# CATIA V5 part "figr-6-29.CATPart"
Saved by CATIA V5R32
Part number: Part1
Bounding box of the stored display mesh (mm): x 0 to 45, y 0 to 76.536, z 0 to 111.001
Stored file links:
  D:\PROJECTS\Project 2022\CATIA V5 6R 2022\Resources\Part Files\c06_catia_v5_6r2022_prt\figr-6-29.CATPart
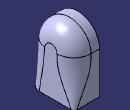
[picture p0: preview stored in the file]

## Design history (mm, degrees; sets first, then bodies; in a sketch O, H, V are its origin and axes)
Body1 (main body)
  Sketch1 on yz-plane, origin (0, 0, 0), H (0, 1, 0), V (0, 0, 1)
    line L1 (0, 0) -> (76.5361, 0)
    line L2 (76.5361, 0) -> (76.5361, 72.7325)
    line L3 (0, 0) -> (0, 72.7325)
    arc A1 centre (38.2681, 72.7325) radius 38.2681 from (76.5361, 72.7325) to (0, 72.7325) ccw
    horizontal: L1 H
    vertical: L2 V, L3 V
    tangency: A1 L3, A1 L2
  Pad1: profile Sketch1, direction (1, 0, 0), length 45
  Fillet1: on edge [face of Pad1 | face of Pad1] (x3)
